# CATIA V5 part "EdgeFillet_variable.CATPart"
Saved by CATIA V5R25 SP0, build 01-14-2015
Part number: Part1
Bounding box of the stored display mesh (mm): x -55 to 55, y -155 to 25.782, z -44.572 to 40
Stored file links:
  E:\cadcim\GSD_cat_v5-6r2014\Part_files\EdgeFillet_variable.CATPart
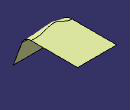
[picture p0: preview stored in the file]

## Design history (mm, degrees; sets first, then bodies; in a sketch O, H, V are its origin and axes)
Body1 (main body)
  Sketch1 on yz-plane, origin (0, 0, 0), H (0, 1, 0), V (0, 0, 1)
    point P1 (25.7818, 40)
    line L1 (25.7818, 40) -> (-124.2182, 40)
    line L2 (-124.2182, 40) -> (-155, -44.5723)
    point P3 (-155, -44.5723)
    length L1 = 150
    length L2 = 90
    angle L2 L1 = 110
    distance P1 H = 40
    distance P3 V = 155
    horizontal: L1 H
  Extrude1: Element1 Sketch1, Lim1 55, Lim2 55
  Plane1: type Offset, RefPlane yz-plane, Offset 20
  Point1: type OnCurve, Support edge [face of Extrude1 from Sketch1.L1 | face of Extrude1 from Sketch1.L2], Length 0
  Fillet1: radius 20, on edge [face of Extrude1 from Sketch1.L1 | face of Extrude1 from Sketch1.L2]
